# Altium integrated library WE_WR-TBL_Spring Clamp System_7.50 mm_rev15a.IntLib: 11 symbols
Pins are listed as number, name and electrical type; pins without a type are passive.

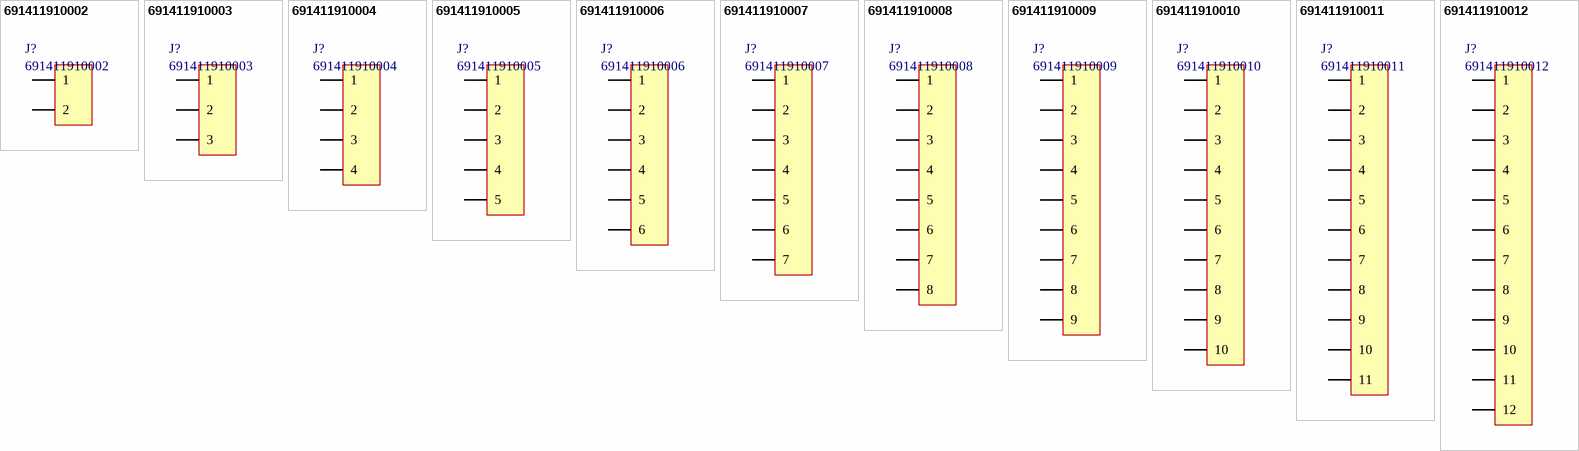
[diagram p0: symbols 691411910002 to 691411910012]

## 691411910002
designator J?
Horizontal Cable Entry Screwless, Serie 4119 - 7.5 mm; Manufacturer: Wurth Elektronik; ComponentLink1 Description: Manufacturer; ComponentLink2 Description: Datasheet; NoPins: 2
footprint 691411910002 (Serie 4119 - 7.50 mm _ 2 pins)
pins: 1, 2

## 691411910003
designator J?
Horizontal Cable Entry Screwless, Serie 4119 - 7.5 mm; Manufacturer: Wurth Elektronik; ComponentLink1 Description: Manufacturer; ComponentLink2 Description: Datasheet; NoPins: 3
footprint 691411910003 (Serie 4119 - 7.50 mm _ 3 pins)
pins: 1, 2, 3

## 691411910004
designator J?
Horizontal Cable Entry Screwless, Serie 4119 - 7.5 mm; Manufacturer: Wurth Elektronik; ComponentLink1 Description: Manufacturer; ComponentLink2 Description: Datasheet; NoPins: 4
footprint 691411910004 (Serie 4119 - 7.50 mm _ 4 pins)
pins: 1, 2, 3, 4

## 691411910005
designator J?
Horizontal Cable Entry Screwless, Serie 4119 - 7.5 mm; Manufacturer: Wurth Elektronik; ComponentLink1 Description: Manufacturer; ComponentLink2 Description: Datasheet; NoPins: 5
footprint 691411910005 (Serie 4119 - 7.50 mm _ 5 pins)
pins: 1, 2, 3, 4, 5

## 691411910006
designator J?
Horizontal Cable Entry Screwless, Serie 4119 - 7.5 mm; Manufacturer: Wurth Elektronik; ComponentLink1 Description: Manufacturer; ComponentLink2 Description: Datasheet; NoPins: 6
footprint 691411910006 (Serie 4119 - 7.50 mm _ 6 pins)
pins: 1, 2, 3, 4, 5, 6

## 691411910007
designator J?
Horizontal Cable Entry Screwless, Serie 4119 - 7.5 mm; Manufacturer: Wurth Elektronik; ComponentLink1 Description: Manufacturer; ComponentLink2 Description: Datasheet; NoPins: 7
footprint 691411910007 (Serie 4119 - 7.50 mm _ 7 pins)
pins: 1, 2, 3, 4, 5, 6, 7

## 691411910008
designator J?
Horizontal Cable Entry Screwless, Serie 4119 - 7.5 mm; Manufacturer: Wurth Elektronik; ComponentLink1 Description: Manufacturer; ComponentLink2 Description: Datasheet; NoPins: 8
footprint 691411910008 (Serie 4119 - 7.50 mm _ 8 pins)
pins: 1, 2, 3, 4, 5, 6, 7, 8

## 691411910009
designator J?
Horizontal Cable Entry Screwless, Serie 4119 - 7.5 mm; Manufacturer: Wurth Elektronik; ComponentLink1 Description: Manufacturer; ComponentLink2 Description: Datasheet; NoPins: 9
footprint 691411910009 (Serie 4119 - 7.50 mm _ 9 pins)
pins: 1, 2, 3, 4, 5, 6, 7, 8, 9

## 691411910010
designator J?
Horizontal Cable Entry Screwless, Serie 4119 - 7.5 mm; Manufacturer: Wurth Elektronik; ComponentLink1 Description: Manufacturer; ComponentLink2 Description: Datasheet; NoPins: 10
footprint 691411910010 (Serie 4119 - 7.50 mm _ 10 pins)
pins: 1, 2, 3, 4, 5, 6, 7, 8, 9, 10

## 691411910011
designator J?
Horizontal Cable Entry Screwless, Serie 4119 - 7.5 mm; Manufacturer: Wurth Elektronik; ComponentLink1 Description: Manufacturer; ComponentLink2 Description: Datasheet; NoPins: 11
footprint 691411910011 (Serie 4119 - 7.50 mm _ 11 pins)
pins: 1, 2, 3, 4, 5, 6, 7, 8, 9, 10, 11

## 691411910012
designator J?
Horizontal Cable Entry Screwless, Serie 4119 - 7.5 mm; Manufacturer: Wurth Elektronik; ComponentLink1 Description: Manufacturer; ComponentLink2 Description: Datasheet; NoPins: 12
footprint 691411910012 (Serie 4119 - 7.50 mm _ 12 pins)
pins: 1, 2, 3, 4, 5, 6, 7, 8, 9, 10, 11, 12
